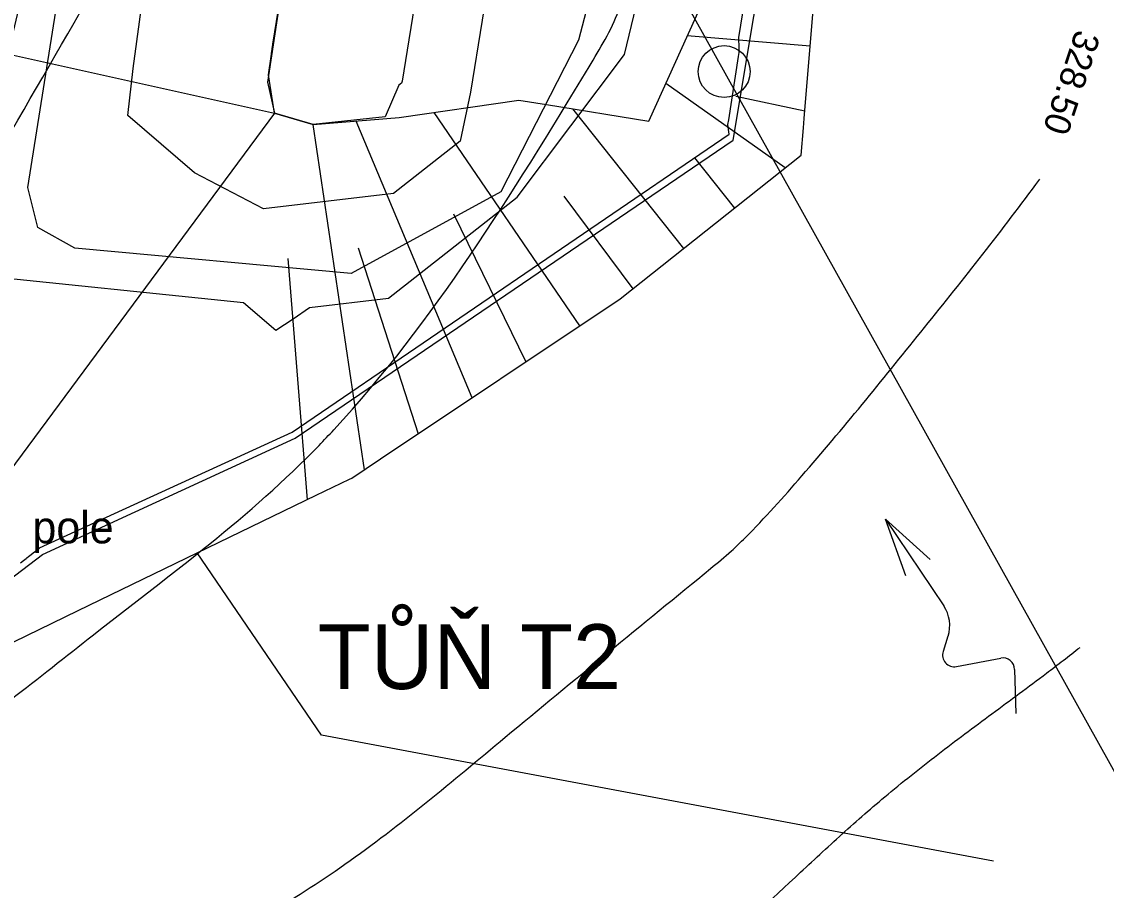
# Model space of a CAD drawing. Extents: x -564037 to -563827, y -1163561 to -1163412.
# Drawn here: x -563926.34 to -563905.42, y -1163504.15 to -1163487.4 of the extents above; entities that cross this region are included whole.
import ezdxf

# ---------------------------------------------------------------- set-up
doc = ezdxf.new("R2010")
doc.units = 0
for name, color, linetype in [('4', 7, 'Continuous'), ('5', 7, 'Continuous'), ('_popis staničení RT1', 7, 'Continuous'), ('Default', 7, 'Continuous'), ('Line', 7, 'Continuous'), ('podélný profil', 7, 'Continuous'), ('Vrstva 24', 7, 'Continuous'), ('Vrstva 25', 7, 'Continuous'), ('Vrstva 26', 7, 'Continuous'), ('Vrstva 40', 7, 'Continuous')]:
    doc.layers.add(name, color=color, linetype=linetype)

msp = doc.modelspace()

# ---------------------------------------------------------------- linework, layer by layer
for points in [[(-563930.469, -1163501.126), (-563927.863, -1163499.14), (-563925.937, -1163497.674), (-563921.059, -1163495.43), (-563912.613, -1163489.681), (-563911.421, -1163482.517), (-563913.266, -1163479.715), (-563914.137, -1163478.749), (-563916.309, -1163476.467), (-563917.281, -1163475.995), (-563923.761, -1163471.506), (-563924, -1163472.797), (-563925.435, -1163477.844), (-563927.008, -1163483.992), (-563927.659, -1163487.507), (-563928.13, -1163490.05), (-563928.806, -1163493.379), (-563930.34, -1163499.841), (-563930.622, -1163501.15)], [(-563915.586, -1163481.384), (-563914.537, -1163483.686), (-563915.595, -1163487.753), (-563917.092, -1163490.681), (-563919.984, -1163492.255), (-563925.31, -1163491.764), (-563926.027, -1163491.364), (-563926.218, -1163490.597), (-563925.375, -1163485.285), (-563924.678, -1163482.734), (-563924.029, -1163478.524), (-563922.899, -1163477.259), (-563919.326, -1163477.602), (-563916.674, -1163478.991)]]:
    msp.add_lwpolyline(points, close=True)
for points in [[(-563917.911, -1163481.802), (-563919.001, -1163488.543), (-563919.009, -1163488.581), (-563919.062, -1163488.623), (-563919.326, -1163489.233), (-563920.716, -1163489.381), (-563921.461, -1163489.159), (-563921.575, -1163488.419), (-563921.52, -1163488.022), (-563921.519, -1163488.013), (-563921.518, -1163488.005), (-563921.517, -1163487.995), (-563921.516, -1163487.988), (-563921.515, -1163487.978), (-563921.514, -1163487.974), (-563921.514, -1163487.97), (-563921.514, -1163487.97), (-563921.511, -1163487.953), (-563921.508, -1163487.937), (-563921.508, -1163487.935), (-563921.505, -1163487.919), (-563921.504, -1163487.912), (-563921.503, -1163487.901), (-563921.501, -1163487.884), (-563921.498, -1163487.865), (-563921.497, -1163487.859), (-563921.496, -1163487.847), (-563921.493, -1163487.828), (-563920.465, -1163481.469)], [(-563927.306, -1163492.273), (-563922.057, -1163492.813), (-563921.435, -1163493.345), (-563921.102, -1163493.131), (-563920.787, -1163492.909), (-563919.265, -1163492.727), (-563916.779, -1163490.783), (-563914.71, -1163488.029), (-563913.607, -1163483.439)], [(-563926.357, -1163497.832), (-563926.303, -1163497.79), (-563926.252, -1163497.75), (-563926.241, -1163497.741), (-563926.203, -1163497.713), (-563926.157, -1163497.677), (-563926.114, -1163497.643), (-563926.073, -1163497.611), (-563926.047, -1163497.591), (-563926.04, -1163497.586), (-563926.033, -1163497.581), (-563925.996, -1163497.552), (-563925.993, -1163497.549), (-563921.117, -1163495.312), (-563912.692, -1163489.565), (-563912.719, -1163489.382), (-563912.7, -1163489.29), (-563912.508, -1163488.065), (-563912.499, -1163487.988), (-563912.497, -1163487.906), (-563912.506, -1163487.699), (-563911.986, -1163484.484)], [(-563921.157, -1163485.676), (-563921.598, -1163488.562), (-563921.461, -1163489.159), (-563920.716, -1163489.381), (-563919.058, -1163489.245), (-563919.058, -1163489.245), (-563919.058, -1163489.245), (-563916.75, -1163488.907), (-563916.212, -1163488.994), (-563914.24, -1163489.313), (-563912.713, -1163485.924)], [(-563917.23, -1163485.969), (-563917.681, -1163488.756), (-563917.877, -1163489.7), (-563919.165, -1163490.707), (-563921.676, -1163491.008), (-563923.002, -1163490.31), (-563924.293, -1163489.206), (-563924.187, -1163488.301), (-563923.991, -1163486.868)], [(-563907.591, -1163503.589), (-563920.552, -1163501.157), (-563922.95, -1163497.645)]]:
    msp.add_lwpolyline(points)
at = {"layer": '5'}
msp.add_line((-563921.324, -1163473.035), (-563903.913, -1163504.291), dxfattribs=at)
at = {"layer": '_popis staničení RT1'}
msp.add_circle((-563912.788, -1163488.358), 0.5, dxfattribs=at)
at = {"layer": 'Default'}
msp.add_lwpolyline([(-563925.948, -1163485.244), (-563926.867, -1163489.1), (-563927.916, -1163493.212), (-563928.032, -1163493.665), (-563928.034, -1163493.674), (-563928.134, -1163494.067), (-563928.211, -1163494.367), (-563929.345, -1163497.668), (-563930.401, -1163500.745), (-563930.002, -1163500.645), (-563928.239, -1163500.208), (-563925.246, -1163498.757), (-563920.654, -1163496.532), (-563920.013, -1163496.222), (-563919.971, -1163496.201), (-563919.419, -1163495.832), (-563914.794, -1163492.742), (-563911.305, -1163489.972), (-563911.26, -1163489.446), (-563911.245, -1163489.265), (-563911.055, -1163487.019)], dxfattribs=at)
at = {"layer": 'Line'}
for p, q in [((-563911.127, -1163487.869), (-563913.499, -1163487.668)), ((-563926.609, -1163488.017), (-563921.461, -1163489.159)), ((-563911.61, -1163490.214), (-563913.912, -1163488.587)), ((-563912.565, -1163488.834), (-563911.232, -1163489.114)), ((-563921.461, -1163489.159), (-563929.957, -1163500.634)), ((-563915.571, -1163493.261), (-563918.383, -1163489.146)), ((-563913.568, -1163491.769), (-563915.706, -1163489.076)), ((-563919.728, -1163496.039), (-563920.716, -1163489.381)), ((-563917.65, -1163494.65), (-563919.887, -1163489.313)), ((-563913.357, -1163490.024), (-563912.589, -1163490.991)), ((-563915.878, -1163490.76), (-563914.547, -1163492.546)), ((-563918.005, -1163491.102), (-563916.61, -1163493.956)), ((-563919.844, -1163491.761), (-563918.689, -1163495.344)), ((-563921.206, -1163491.965), (-563920.833, -1163496.619))]:
    msp.add_line(p, q, dxfattribs=at)
at = {"layer": 'podélný profil'}
for points in [[(-563909.281, -1163498.085), (-563909.675, -1163496.991), (-563908.812, -1163497.771)], [(-563909.675, -1163496.991), (-563908.552, -1163498.667)], [(-563908.47, -1163499.251), (-563908.564, -1163499.544)], [(-563908.308, -1163499.835), (-563907.453, -1163499.674)], [(-563907.186, -1163499.89), (-563907.162, -1163500.74)]]:
    msp.add_lwpolyline(points, dxfattribs=at)
for centre, radius, start, end in [((-563909.114, -1163499.043), 0.677, 342.1284, 33.8229), ((-563908.35, -1163499.613), 0.226, 162.1305, 280.6775), ((-563907.411, -1163499.896), 0.226, 1.534, 100.6512)]:
    msp.add_arc(centre, radius, start, end, dxfattribs=at)
at = {"layer": 'Vrstva 24'}
for points in [[(-563903.419, -1163497.029), (-563902.125, -1163495.59), (-563900.744, -1163494.039), (-563899.345, -1163492.505), (-563898.448, -1163491.553), (-563897.897, -1163490.941), (-563897.635, -1163490.622), (-563897.383, -1163490.29), (-563897.001, -1163489.401), (-563896.398, -1163486.71), (-563896.305, -1163486.212), (-563896.276, -1163485.962), (-563896.268, -1163485.713), (-563896.394, -1163485.294), (-563896.666, -1163484.924), (-563897.969, -1163483.548), (-563899.309, -1163482.237), (-563900.743, -1163480.898), (-563903.659, -1163478.289), (-563907.403, -1163474.951), (-563909.511, -1163473.024), (-563914.099, -1163468.742), (-563916.271, -1163466.637)], [(-563939.075, -1163507.623), (-563938.225, -1163507.164), (-563937.324, -1163506.641), (-563936.436, -1163506.097), (-563935.549, -1163505.552), (-563934.649, -1163505.03), (-563930.625, -1163502.906), (-563929.451, -1163502.347), (-563928.196, -1163501.635), (-563924.955, -1163499.225), (-563920.602, -1163495.57), (-563920.316, -1163495.267), (-563915.394, -1163488.268), (-563914.823, -1163487.183), (-563914.579, -1163485.87), (-563914.81, -1163484.102), (-563915.208, -1163482.646), (-563915.847, -1163480.252), (-563916.025, -1163479.9), (-563916.675, -1163479.113), (-563917.077, -1163478.648)], [(-563942.475, -1163518.079), (-563940.112, -1163517.387), (-563935.904, -1163515.974), (-563933.959, -1163515.268), (-563929.245, -1163513.665), (-563925.032, -1163512.173), (-563922.819, -1163511.166), (-563919.003, -1163509.075), (-563915.156, -1163506.928), (-563914.035, -1163506.214), (-563913.139, -1163505.478), (-563911.421, -1163503.905), (-563910.565, -1163503.115), (-563909.689, -1163502.349), (-563908.668, -1163501.532), (-563907.622, -1163500.746), (-563906.572, -1163499.965), (-563905.922, -1163499.466)]]:
    msp.add_spline(points, degree=3, dxfattribs=at)
at = {"layer": 'Vrstva 26'}
for points in [[(-563938.486, -1163500.528), (-563938.463, -1163500.513), (-563937.665, -1163500.022), (-563936.97, -1163499.566), (-563930.777, -1163494.949), (-563928.884, -1163493.45), (-563928.656, -1163493.192), (-563928.195, -1163492.447), (-563924.372, -1163485.735), (-563923.788, -1163484.5), (-563923.604, -1163483.639), (-563923.611, -1163481.604), (-563923.712, -1163481.017), (-563924.518, -1163478.475), (-563924.689, -1163477.919), (-563924.751, -1163477.798), (-563925.518, -1163476.583), (-563926.306, -1163475.384), (-563927.092, -1163474.184), (-563927.851, -1163472.968), (-563928.532, -1163471.813), (-563929.192, -1163470.645), (-563929.849, -1163469.476), (-563930.525, -1163468.317), (-563930.688, -1163468.07), (-563931.156, -1163467.471), (-563931.276, -1163467.321)], [(-563940.525, -1163513.198), (-563938.9, -1163512.504), (-563932.611, -1163509.84), (-563931.885, -1163509.567), (-563930.901, -1163509.188), (-563926.659, -1163507.216), (-563923.334, -1163505.549), (-563921.652, -1163504.643), (-563920.105, -1163503.651), (-563917.012, -1163501.201), (-563913.048, -1163497.944), (-563912.649, -1163497.606), (-563912.385, -1163497.353), (-563911.289, -1163496.159), (-563908.991, -1163493.383), (-563906.775, -1163490.536), (-563906.699, -1163490.433)], [(-563906.28, -1163515.803), (-563905.884, -1163515.571), (-563902.883, -1163513.741), (-563899.929, -1163512.038), (-563897.928, -1163511.018), (-563895.553, -1163509.778), (-563893.055, -1163508.246), (-563892.353, -1163507.782), (-563891.657, -1163507.311), (-563890.96, -1163506.841), (-563890.257, -1163506.379), (-563888.16, -1163505.094), (-563886.21, -1163504.031), (-563880.965, -1163501.085), (-563878.454, -1163499.578), (-563877.23, -1163498.772), (-563876.032, -1163497.922), (-563874.901, -1163496.941), (-563873.614, -1163495.651), (-563873.276, -1163495.107), (-563873.154, -1163494.587), (-563873.048, -1163494.066), (-563872.865, -1163493.019), (-563872.827, -1163492.778)]]:
    msp.add_spline(points, degree=3, dxfattribs=at)

# ---------------------------------------------------------------- texts
at = {"layer": '4'}
msp.add_text('TŮŇ T2', height=1.25, rotation=360, dxfattribs=at).set_placement((-563920.624, -1163500.27))
at = {"layer": 'Vrstva 25'}
msp.add_text('328.50', height=0.5, rotation=251.6075, dxfattribs=at).set_placement((-563905.999, -1163487.525))
at = {"layer": 'Vrstva 40'}
msp.add_text('pole', height=0.62, dxfattribs=at).set_placement((-563926.13, -1163497.46))

doc.saveas('drawing.dxf')
